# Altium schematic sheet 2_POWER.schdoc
size 309 x 223 mm; Symbol: Sheet-Symbol_A4; Device: Sheet-Symbol_A4; @Page Name: POWER; @Create Date: 2023-05-13; @Page Count: 3; @Page No: 1; @Project Name: STM32_Wave&DSO; @Schematic Name: STM32_Wave&amp;DSO; @Update Date: 2023-05-14; Company: DGUT; Drawed: veis; Page Size: A4; Version: V1.0
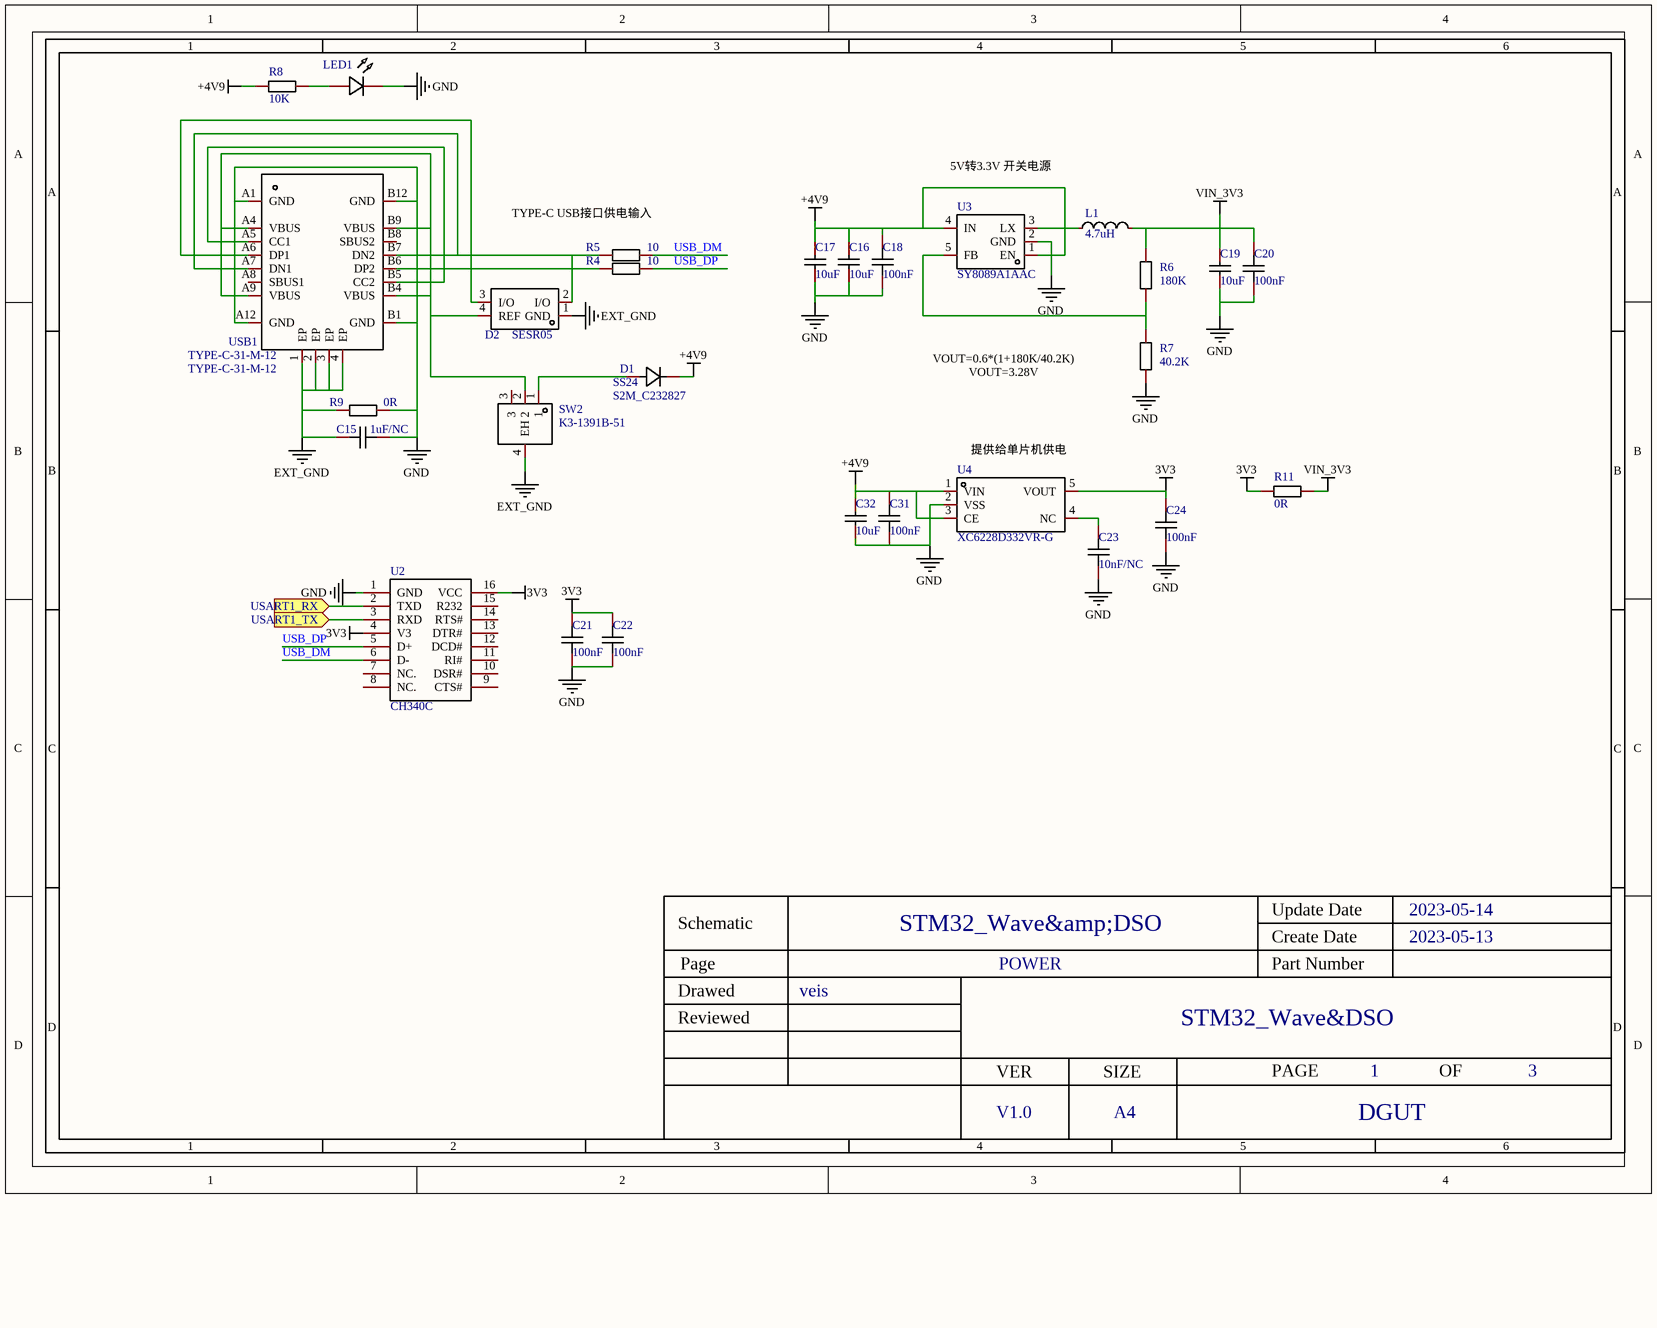
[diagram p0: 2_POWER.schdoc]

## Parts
C15  1uF/NC  [C0603]
C16  10uF  [C0805]
C17  10uF  [C0805]
C18  100nF  [C0603]
C19  10uF  [C0805]
C20  100nF  [C0603]
C21  100nF  [C0603]
C22  100nF  [C0603]
C23  10nF/NC  [C0603]
C24  100nF  [C0603]
C31  100nF  [C0603]
C32  10uF  [C0805]
D1  SS24  [SMB_L4.6-W3.6-LS5.3-RD]
D2  SESR05  [SOT-143-4_L2.9-W1.3-P1.92-LS2.3-BL]
L1  4.7uH  [L2520]
LED1  LED_0603-R  [LED_0603]  (value not drawn)
R4  10  [R0603]
R5  10  [R0603]
R6  180K  [R0603]
R7  40.2K  [R0603]
R8  10K  [R0603]
R9  0R  [R0603]
R11  0R  [R0603]
SW2  K3-1391B-51  [SW-TH_K3-1391B-51]
U2  CH340C  [SOP-16_L10.0-W3.9-P1.27-LS6.0-BL]
U3  SY8089A1AAC  [TSOT-23-5_L2.9-W1.6-P0.95-LS2.8-BR]
U4  XC6228D332VR-G  [TSOT-23-5_L2.9-W1.6-P0.95-LS2.8-BR]
USB1  TYPE-C-31-M-12  [USB-C_SMD-TYPE-C-31-M-12]

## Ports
USART1_RX (in), USART1_TX (in)

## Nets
3V3: C21.2 C22.2 C24.2 R11.1 U2.4(V3) U2.16(VCC) U4.5(VOUT)
+4V9: C16.2 C17.2 C18.2 C31.2 C32.2 D1.1(K) R8.2 U3.1(EN) U3.4(IN) U4.1(VIN) U4.3(CE)
EXT_GND: C15.1 D2.1(GND) R9.1 SW2.4(EH) USB1.1(EP) USB1.2(EP) USB1.3(EP) USB1.4(EP)
GND: C15.2 C16.1 C17.1 C18.1 C19.1 C20.1 C21.1 C22.1 C23.1 C24.1 C31.1 C32.1 LED1.1(C) R7.2 R9.2 U2.1(GND) U3.2(GND) U4.2(VSS) USB1.A1(GND) USB1.A12(GND) USB1.B1(GND) USB1.B12(GND)
VIN_3V3: C19.2 C20.2 L1.2 R6.1 R11.2
USART1_RX: U2.2(TXD) ; port USART1_RX
USART1_TX: U2.3(RXD) ; port USART1_TX
USB_DM: R5.1 U2.6(D-)
USB_DP: R4.1 U2.5(D+)
NetC23_2: C23.2 U4.4(NC)
NetD1_2: D1.2(A) SW2.1
NetD2_2: D2.2(I/O) R5.2 USB1.A7(DN1) USB1.B7(DN2)
NetD2_3: D2.3(I/O) R4.2 USB1.A6(DP1) USB1.B6(DP2)
NetD2_4: D2.4(REF) SW2.2 USB1.A4(VBUS) USB1.A9(VBUS) USB1.B4(VBUS) USB1.B9(VBUS)
NetL1_1: L1.1 U3.3(LX)
NetLED1_2: LED1.2(A) R8.1
NetR6_2: R6.2 R7.1 U3.5(FB)
NetUSB1_A5: USB1.A5(CC1) USB1.B5(CC2)

Not connected (* = marked no-connect by the designer): SW2 3; U2 7(NC.) 8(NC.) 9(CTS#) 10(DSR#) 11(RI#) 12(DCD#) 13(DTR#) 14(RTS#) 15(R232); USB1 A8(SBUS1) B8(SBUS2)

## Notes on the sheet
- 5V转3.3V 开关电源
- TYPE-C USB接口供电输入
- (near U4) VOUT=0.6*(1+180K/40.2K)
  VOUT=3.28V
- (near U4) 提供给单片机供电

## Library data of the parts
C15 = CAP_0603: Symbol: CapAcitance; Convert to PCB: yes
C16 C17 C19 C32 = GRM21BR61H106KE43L: 容值:10uF;精度:±10%;额定电压:50V;材质(温度系数):X5R;; Manufacturer: muRata(村田); Add into BOM: yes; Tolerance: ±10%; Voltage Rated: 50V; Temperature Coefficient: X5R
C18 C20-C24 C31 = CC0603KRX7R9BB104: 容值:100nF;精度:±10%;额定电压:50V;材质(温度系数):X7R;; Manufacturer: YAGEO(国巨); Add into BOM: yes; Tolerance: ±10%; Voltage Rated: 50V; Temperature Coefficient: X7R
D1 = S2M_C232827: 二极管配置:-;直流反向耐压(Vr):1kV;平均整流电流(Io):2A;正向压降(Vf):1.15V@2A;反向电流(Ir):1uA@1kV;; Manufacturer: onsemi(安森美); Add into BOM: yes; Reverse Voltage (Vr): 1kV; Average Rectified Current (Io): 2A
D2 = SESR05: Manufacturer: SEMIWARE(赛米微尔); Add into BOM: yes
L1 = TFM252012ALMA4R7MTAA: 电感值:4.7uH;精度:±20%;额定电流:1.6A;; Manufacturer: TDK; Add into BOM: yes; Tolerance: ±20%; Rated Current: 1.6A; DC Resistance (DCR): 180mΩ
LED1 = LED_0603-R: Symbol: LED_R; Convert to PCB: yes
R4-R9 R11 = Res_0603: Symbol: 电阻; Convert to PCB: yes
SW2 = K3-1391B-51: 额定电流(AC):5A;额定电压(AC):120V;电路结构:单刀双掷;安装方式:卧插;机械寿命:3万次;开关颜色:黑色;; Manufacturer: 韩国韩荣; Add into BOM: yes; Current Rating (AC): 5A; Voltage Rating (AC): 120V; Circuit: 单刀双掷; Mechanical Life: 3万次; Actuator Color: 黑色; Actuator Style: 矩形柱状; Pin Style: PC引脚; Switch Length: 13.3mm; Switch Width: 6mm; Switch Height: 6.6mm
U2 = CH340C: 应用功能:Transceiver;接口协议:USB 2.0;数据速率:2Mbps;供电电压:3.3V；5V;; Manufacturer: WCH(南京沁恒); Add into BOM: yes; Protocol: USB 2.0; Data Rate: 2Mbps
U3 = SY8089A1AAC: Manufacturer: silergy(矽力杰); Add into BOM: yes
U4 = XC6228D122VR-G: 输出类型:固定;输出极性:正;最大输入电压:5.5V;输出电压:1.2V~1.2V;输出电流:300mA;电源纹波抑制比(PSRR):80dB@(1kHz);; Manufacturer: TOREX(特瑞仕); Add into BOM: yes; Output Type: 固定; Output Polarity: 正; Number of Outputs: 1; Maximum Input Voltage: 5.5V; Dropout Voltage: 630mV@(300mA); Output Current: 300mA
USB1 = TYPE-C-31-M-12: 连接器类型:Type-C;标准:-;公母:母座;触点数量:16;端口数量:1;安装方式:-;额定电流 - 电源:5A;触头材质:-;触头镀层:-;工作温度范围:-;焊接温度(最大值):-;; Manufacturer: 韩国韩荣; Add into BOM: yes; Connector Type: Type-C; Gender: 母座; Number of Contacts: 16; Number of Ports: 1; Current Rating - Power (Max): 5A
